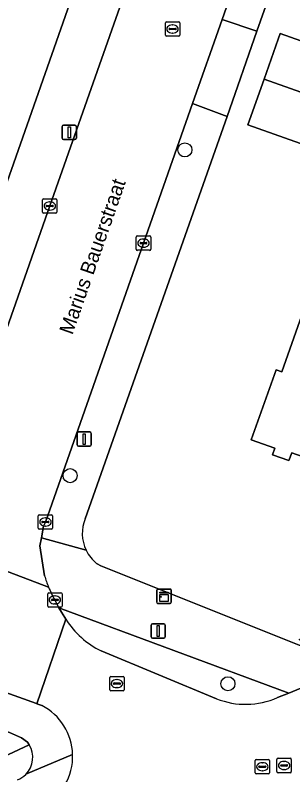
# Model space of a CAD drawing. Extents: x 163266 to 164362, y 381528 to 382286.
# Drawn here: x 163785.5 to 163804.8, y 381685.3 to 381738.1 of the extents above; entities that cross this region are included whole.
import ezdxf

# ---------------------------------------------------------------- set-up
doc = ezdxf.new("R2010")
doc.units = 0
for name, color, linetype in [('IMGEO_Boom', 7, 'Continuous'), ('IMGEO_Erf', 7, 'Continuous'), ('IMGEO_Groenvoorziening', 7, 'Continuous'), ('IMGEO_Kast', 7, 'Continuous'), ('IMGEO_Kolk', 7, 'Continuous'), ('IMGEO_Lichtmast', 7, 'Continuous'), ('IMGEO_Openbare_ruimte_label', 7, 'Continuous'), ('IMGEO_Pand', 7, 'Continuous'), ('IMGEO_Rijbaan_lokaal_open', 7, 'Continuous'), ('IMGEO_Rioolput', 7, 'Continuous'), ('IMGEO_Voetpad_open', 7, 'Continuous')]:
    doc.layers.add(name, color=color, linetype=linetype)

msp = doc.modelspace()

# ---------------------------------------------------------------- linework, layer by layer
at = {"layer": 'IMGEO_Boom'}
for centre in [(163797.269, 381728.696), (163789.28, 381706.058), (163800.268, 381691.599)]:
    msp.add_circle(centre, 0.489, dxfattribs=at)
at = {"layer": 'IMGEO_Erf'}
for points in [[(163812.165, 381764.712), (163806.923, 381750), (163802.269, 381736.937), (163800.206, 381731.005), (163790.326, 381703.056)], [(163777.847, 381706.456), (163793.157, 381750)], [(163791.151, 381699.94), (163791.408, 381699.801), (163806.152, 381693.919), (163806.177, 381693.979), (163805.225, 381694.676), (163831.794, 381705.491), (163841.15, 381710.28)]]:
    msp.add_lwpolyline(points, dxfattribs=at)
for points in [[(163812.472, 381727.394), (163810.675, 381728.03), (163810.431, 381727.341), (163801.659, 381730.443), (163802.779, 381733.609), (163803.764, 381736.396), (163803.897, 381736.771), (163812.668, 381733.669), (163811.55, 381730.506), (163813.348, 381729.87)], [(163815.301, 381718.07), (163813.331, 381712.499), (163812.084, 381712.94), (163809.721, 381706.258), (163811.07, 381705.781), (163810.948, 381705.435), (163804.707, 381707.643), (163804.516, 381707.104), (163803.376, 381707.507), (163803.537, 381707.961), (163801.891, 381708.542), (163803.614, 381713.412), (163804.015, 381713.27), (163806.641, 381720.695), (163806.167, 381720.862), (163806.29, 381721.211), (163808.642, 381720.379), (163808.82, 381720.884), (163809.958, 381720.482), (163809.794, 381720.018)]]:
    msp.add_lwpolyline(points, close=True, dxfattribs=at)
for centre, radius, start, end in [((163792.797, 381702.044), 2.67, 157.7302, 205.8989), ((163792.792, 381702.037), 2.663, 205.7933, 231.9423)]:
    msp.add_arc(centre, radius, start, end, dxfattribs=at)
at = {"layer": 'IMGEO_Groenvoorziening'}
for points in [[(163788.503, 381696.878), (163788.683, 381696.565), (163788.902, 381696.202), (163788.981, 381696.076)], [(163803.705, 381690.635), (163804.494, 381690.943), (163788.503, 381696.878)], [(163791.444, 381693.885), (163799.475, 381690.558)], [(163786.431, 381687.36), (163746.827, 381668.861), (163743.582, 381666.907), (163741.092, 381665.064), (163738.545, 381663.071), (163732.674, 381659.172), (163735.245, 381658.18)]]:
    msp.add_lwpolyline(points, dxfattribs=at)
msp.add_lwpolyline([(163786.431, 381687.36), (163786.311, 381687.532), (163785.889, 381687.845), (163785.054, 381688.219), (163774.893, 381691.766), (163774.456, 381690.384), (163772.402, 381684.557), (163769.505, 381685.578), (163766.609, 381686.599), (163763.712, 381687.62), (163760.816, 381688.64), (163757.919, 381689.661), (163755.022, 381690.682), (163752.126, 381691.703), (163749.229, 381692.724), (163745.303, 381694.051), (163732.674, 381659.172), (163738.545, 381663.071), (163741.092, 381665.064), (163743.582, 381666.907), (163746.827, 381668.861)], close=True, dxfattribs=at)
for centre, radius, start, end in [((163794.096, 381699.346), 6.071, 212.5919, 244.0977), ((163801.499, 381695.612), 5.445, 248.1798, 293.9059), ((163784.99, 381686.482), 1.687, 315.6611, 31.359), ((163784.982, 381686.499), 1.705, 291.6153, 315.4489)]:
    msp.add_arc(centre, radius, start, end, dxfattribs=at)
at = {"layer": 'IMGEO_Kast'}
for p, q in [((163795.32, 381697.255), (163795.32, 381698.096)), ((163795.32, 381698.096), (163795.32, 381697.255)), ((163795.395, 381698.18), (163796.236, 381698.18)), ((163796.236, 381698.18), (163795.395, 381698.18)), ((163796.32, 381698.105), (163796.32, 381697.264)), ((163796.32, 381697.264), (163796.32, 381698.105)), ((163796.245, 381697.18), (163795.404, 381697.18)), ((163795.404, 381697.18), (163796.245, 381697.18))]:
    msp.add_line(p, q, dxfattribs=at)
for points in [[(163795.515, 381697.97), (163796.115, 381697.97), (163796.115, 381697.885), (163795.515, 381697.885), (163795.515, 381697.97)], [(163795.515, 381697.795), (163796.115, 381697.795), (163796.115, 381697.306), (163795.515, 381697.306), (163795.515, 381697.795)]]:
    msp.add_lwpolyline(points, dxfattribs=at)
msp.add_circle((163795.599, 381697.644), 0.0377, dxfattribs=at)
for centre, start, end in [((163795.398, 381698.102), 92.4484, 184.2845), ((163795.398, 381698.102), 92.4484, 184.2845), ((163796.242, 381698.102), 2.4484, 94.2845), ((163796.242, 381698.102), 2.4484, 94.2845), ((163795.398, 381697.258), 182.4484, 274.2845), ((163795.398, 381697.258), 182.4484, 274.2845), ((163796.242, 381697.258), 272.4484, 4.2845), ((163796.242, 381697.258), 272.4484, 4.2845)]:
    msp.add_arc(centre, 0.0779, start, end, dxfattribs=at)
at = {"layer": 'IMGEO_Kolk'}
for p, q in [((163787.362, 381724.37), (163787.362, 381725.222)), ((163787.437, 381725.296), (163788.289, 381725.296)), ((163787.664, 381724.839), (163788.062, 381724.839)), ((163787.85, 381725.076), (163787.875, 381725.076)), ((163788.363, 381725.222), (163788.363, 381724.37)), ((163787.621, 381724.79), (163787.621, 381724.802)), ((163788.059, 381724.753), (163787.661, 381724.753)), ((163787.873, 381724.516), (163787.848, 381724.516)), ((163788.105, 381724.802), (163788.105, 381724.79)), ((163788.289, 381724.296), (163787.437, 381724.296)), ((163793.886, 381721.789), (163793.886, 381722.641)), ((163793.961, 381722.715), (163794.813, 381722.715)), ((163794.145, 381722.209), (163794.145, 381722.221)), ((163794.188, 381722.258), (163794.586, 381722.258)), ((163794.374, 381722.495), (163794.399, 381722.495)), ((163794.629, 381722.221), (163794.629, 381722.209)), ((163794.887, 381722.641), (163794.887, 381721.789)), ((163794.813, 381721.715), (163793.961, 381721.715)), ((163794.583, 381722.172), (163794.185, 381722.172)), ((163794.397, 381721.935), (163794.372, 381721.935)), ((163787.061, 381702.411), (163787.061, 381703.263)), ((163787.136, 381703.337), (163787.988, 381703.337)), ((163788.062, 381703.263), (163788.062, 381702.411)), ((163787.32, 381702.831), (163787.32, 381702.843)), ((163787.758, 381702.794), (163787.36, 381702.794)), ((163787.363, 381702.88), (163787.761, 381702.88)), ((163787.549, 381703.117), (163787.574, 381703.117)), ((163787.804, 381702.843), (163787.804, 381702.831)), ((163787.988, 381702.337), (163787.136, 381702.337)), ((163787.572, 381702.557), (163787.547, 381702.557)), ((163787.792, 381697.923), (163788.644, 381697.923)), ((163787.717, 381696.997), (163787.717, 381697.849)), ((163787.976, 381697.417), (163787.976, 381697.429)), ((163788.019, 381697.466), (163788.417, 381697.466)), ((163788.205, 381697.703), (163788.23, 381697.703)), ((163788.46, 381697.429), (163788.46, 381697.417)), ((163788.718, 381697.849), (163788.718, 381696.997)), ((163788.644, 381696.923), (163787.792, 381696.923)), ((163788.414, 381697.38), (163788.016, 381697.38)), ((163788.228, 381697.143), (163788.203, 381697.143))]:
    msp.add_line(p, q, dxfattribs=at)
for points in [[(163787.362, 381724.37), (163787.362, 381725.222)], [(163787.437, 381725.296), (163788.289, 381725.296)], [(163788.363, 381725.222), (163788.363, 381724.37)], [(163788.289, 381724.296), (163787.437, 381724.296)], [(163793.886, 381721.789), (163793.886, 381722.641)], [(163793.961, 381722.715), (163794.813, 381722.715)], [(163794.887, 381722.641), (163794.887, 381721.789)], [(163794.813, 381721.715), (163793.961, 381721.715)], [(163787.061, 381702.411), (163787.061, 381703.263)], [(163787.136, 381703.337), (163787.988, 381703.337)], [(163788.062, 381703.263), (163788.062, 381702.411)], [(163787.988, 381702.337), (163787.136, 381702.337)], [(163787.792, 381697.923), (163788.644, 381697.923)], [(163787.717, 381696.997), (163787.717, 381697.849)], [(163788.718, 381697.849), (163788.718, 381696.997)], [(163788.644, 381696.923), (163787.792, 381696.923)]]:
    msp.add_lwpolyline(points, dxfattribs=at)
for centre, radius, start, end in [((163787.439, 381725.22), 0.0765, 91.552, 178.448), ((163787.439, 381725.22), 0.0765, 91.552, 178.448), ((163787.661, 381724.799), 0.0403, 85.8775, 175.7526), ((163788.066, 381724.801), 0.0386, 1.7309, 96.639), ((163788.287, 381725.22), 0.0765, 1.552, 88.448), ((163788.287, 381725.22), 0.0765, 1.552, 88.448), ((163787.439, 381724.372), 0.0765, 181.552, 268.448), ((163787.439, 381724.372), 0.0765, 181.552, 268.448), ((163787.658, 381724.789), 0.0366, 178.938, 274.7102), ((163788.062, 381724.796), 0.043, 264.8664, 352.4533), ((163788.287, 381724.372), 0.0765, 271.552, 358.448), ((163788.287, 381724.372), 0.0765, 271.552, 358.448), ((163793.963, 381722.639), 0.0765, 91.552, 178.448), ((163793.963, 381722.639), 0.0765, 91.552, 178.448), ((163794.185, 381722.218), 0.0403, 85.8775, 175.7526), ((163794.182, 381722.208), 0.0366, 178.938, 274.7102), ((163794.586, 381722.215), 0.043, 264.8664, 352.4533), ((163794.59, 381722.22), 0.0386, 1.7309, 96.639), ((163794.811, 381722.639), 0.0765, 1.552, 88.448), ((163794.811, 381722.639), 0.0765, 1.552, 88.448), ((163793.963, 381721.791), 0.0765, 181.552, 268.448), ((163793.963, 381721.791), 0.0765, 181.552, 268.448), ((163794.811, 381721.791), 0.0765, 271.552, 358.448), ((163794.811, 381721.791), 0.0765, 271.552, 358.448), ((163787.138, 381703.261), 0.0765, 91.552, 178.448), ((163787.138, 381703.261), 0.0765, 91.552, 178.448), ((163787.986, 381703.261), 0.0765, 1.552, 88.448), ((163787.986, 381703.261), 0.0765, 1.552, 88.448), ((163787.36, 381702.84), 0.0403, 85.8775, 175.7526), ((163787.357, 381702.83), 0.0366, 178.938, 274.7102), ((163787.761, 381702.837), 0.043, 264.8664, 352.4533), ((163787.765, 381702.842), 0.0386, 1.7309, 96.639), ((163787.138, 381702.413), 0.0765, 181.552, 268.448), ((163787.138, 381702.413), 0.0765, 181.552, 268.448), ((163787.986, 381702.413), 0.0765, 271.552, 358.448), ((163787.986, 381702.413), 0.0765, 271.552, 358.448), ((163787.794, 381697.847), 0.0765, 91.552, 178.448), ((163787.794, 381697.847), 0.0765, 91.552, 178.448), ((163788.642, 381697.847), 0.0765, 1.552, 88.448), ((163788.642, 381697.847), 0.0765, 1.552, 88.448), ((163788.016, 381697.426), 0.0403, 85.8775, 175.7526), ((163788.013, 381697.416), 0.0366, 178.938, 274.7102), ((163788.417, 381697.423), 0.043, 264.8664, 352.4533), ((163788.421, 381697.428), 0.0386, 1.7309, 96.639), ((163787.794, 381696.999), 0.0765, 181.552, 268.448), ((163787.794, 381696.999), 0.0765, 181.552, 268.448), ((163788.642, 381696.999), 0.0765, 271.552, 358.448), ((163788.642, 381696.999), 0.0765, 271.552, 358.448)]:
    msp.add_arc(centre, radius, start, end, dxfattribs=at)
for centre, major_axis, ratio, start_param, end_param in [((163787.849, 381724.796), (-0.387, 0.002), 0.722429, 4.712389, 7.853982), ((163787.874, 381724.796), (-0.39, 0.002), 0.717154, 1.570796, 4.712389), ((163794.373, 381722.215), (-0.387, 0.002), 0.722429, 4.712389, 7.853982), ((163794.398, 381722.215), (-0.39, 0.002), 0.717154, 1.570796, 4.712389), ((163787.548, 381702.837), (-0.387, 0.002), 0.722429, 4.712389, 7.853982), ((163787.573, 381702.837), (-0.39, 0.002), 0.717154, 1.570796, 4.712389), ((163788.204, 381697.423), (-0.387, 0.002), 0.722429, 4.712389, 7.853982), ((163788.229, 381697.423), (-0.39, 0.002), 0.717154, 1.570796, 4.712389)]:
    msp.add_ellipse(centre, major_axis=major_axis, ratio=ratio, start_param=start_param, end_param=end_param, dxfattribs=at)
at = {"layer": 'IMGEO_Lichtmast'}
for p, q in [((163788.725, 381729.513), (163788.725, 381730.313)), ((163788.725, 381730.313), (163788.725, 381729.513)), ((163788.825, 381730.413), (163789.615, 381730.413)), ((163789.615, 381730.413), (163788.825, 381730.413)), ((163789.715, 381730.313), (163789.715, 381729.513)), ((163789.715, 381729.513), (163789.715, 381730.313)), ((163789.615, 381729.413), (163788.825, 381729.413)), ((163788.825, 381729.413), (163789.615, 381729.413)), ((163789.864, 381709.097), (163790.654, 381709.097)), ((163790.654, 381709.097), (163789.864, 381709.097)), ((163789.764, 381708.197), (163789.764, 381708.997)), ((163789.764, 381708.997), (163789.764, 381708.197)), ((163790.754, 381708.997), (163790.754, 381708.197)), ((163790.754, 381708.197), (163790.754, 381708.997)), ((163790.654, 381708.097), (163789.864, 381708.097)), ((163789.864, 381708.097), (163790.654, 381708.097)), ((163794.915, 381694.86), (163794.915, 381695.66)), ((163794.915, 381695.66), (163794.915, 381694.86)), ((163795.015, 381695.76), (163795.805, 381695.76)), ((163795.805, 381695.76), (163795.015, 381695.76)), ((163795.905, 381695.66), (163795.905, 381694.86)), ((163795.905, 381694.86), (163795.905, 381695.66)), ((163795.805, 381694.76), (163795.015, 381694.76)), ((163795.015, 381694.76), (163795.805, 381694.76))]:
    msp.add_line(p, q, dxfattribs=at)
for points in [[(163789.145, 381730.288), (163789.295, 381730.288), (163789.295, 381729.538), (163789.145, 381729.538), (163789.145, 381730.288)], [(163790.184, 381708.972), (163790.334, 381708.972), (163790.334, 381708.222), (163790.184, 381708.222), (163790.184, 381708.972)], [(163795.335, 381695.635), (163795.485, 381695.635), (163795.485, 381694.885), (163795.335, 381694.885), (163795.335, 381695.635)]]:
    msp.add_lwpolyline(points, dxfattribs=at)
for centre, start, end in [((163788.825, 381730.313), 90, 180), ((163788.825, 381730.313), 90, 180), ((163789.615, 381730.313), 0, 90), ((163789.615, 381730.313), 360, 90), ((163788.825, 381729.513), 180, 270), ((163788.825, 381729.513), 180, 270), ((163789.615, 381729.513), 270, 0), ((163789.615, 381729.513), 270, 0), ((163789.864, 381708.997), 90, 180), ((163789.864, 381708.997), 90, 180), ((163790.654, 381708.997), 0, 90), ((163790.654, 381708.997), 360, 90), ((163789.864, 381708.197), 180, 270), ((163789.864, 381708.197), 180, 270), ((163790.654, 381708.197), 270, 0), ((163790.654, 381708.197), 270, 0), ((163795.015, 381695.66), 90, 180), ((163795.015, 381695.66), 90, 180), ((163795.805, 381695.66), 0, 90), ((163795.805, 381695.66), 360, 90), ((163795.015, 381694.86), 180, 270), ((163795.015, 381694.86), 180, 270), ((163795.805, 381694.86), 270, 0), ((163795.805, 381694.86), 270, 0)]:
    msp.add_arc(centre, 0.1, start, end, dxfattribs=at)
at = {"layer": 'IMGEO_Pand'}
for points in [[(163811.55, 381730.506), (163812.668, 381733.669), (163803.897, 381736.771), (163803.764, 381736.396), (163802.779, 381733.609)], [(163802.779, 381733.609), (163801.659, 381730.443), (163810.431, 381727.341), (163810.675, 381728.03), (163811.55, 381730.506)], [(163810.948, 381705.435), (163811.07, 381705.781), (163809.721, 381706.258), (163812.084, 381712.94), (163813.331, 381712.499), (163815.301, 381718.07), (163809.794, 381720.018), (163809.958, 381720.482), (163808.82, 381720.884), (163808.642, 381720.379), (163806.29, 381721.211), (163806.167, 381720.862), (163806.641, 381720.695), (163804.015, 381713.27), (163803.614, 381713.412), (163801.891, 381708.542), (163803.537, 381707.961), (163803.376, 381707.507), (163804.516, 381707.104), (163804.707, 381707.643)]]:
    msp.add_lwpolyline(points, close=True, dxfattribs=at)
at = {"layer": 'IMGEO_Rijbaan_lokaal_open'}
for points in [[(163802.834, 381767.295), (163802.49, 381766.272), (163795.328, 381745.996), (163787.863, 381724.796), (163781.038, 381705.454), (163780.903, 381705.075)], [(163787.506, 381699.094), (163787.177, 381701.17), (163787.28, 381701.743), (163787.425, 381702.556), (163787.562, 381702.837), (163794.387, 381722.215), (163797.797, 381731.907), (163799.856, 381737.758), (163809.414, 381764.894)], [(163772.976, 381702.56), (163770.962, 381703.367), (163761.526, 381706.688), (163736.775, 381715.394), (163730.618, 381717.411), (163729.531, 381717.818), (163727.274, 381711.194), (163728.377, 381710.805), (163738.302, 381707.424), (163744.653, 381705.184), (163752.662, 381702.365), (163775.707, 381694.245), (163775.935, 381694.11), (163781.991, 381691.984), (163786.943, 381690.215), (163786.955, 381690.211), (163788.981, 381696.076), (163788.902, 381696.202), (163788.683, 381696.565), (163788.503, 381696.878), (163788.218, 381697.423)], [(163787.782, 381698.313), (163777.894, 381702.062)], [(163777.894, 381702.062), (163787.782, 381698.313)], [(163788.981, 381696.076), (163786.955, 381690.211), (163787.32, 381690.079)], [(163813.682, 381689.801), (163815.256, 381690.453), (163813.448, 381694.664), (163808.955, 381692.801), (163804.494, 381690.943), (163803.705, 381690.635)], [(163799.475, 381690.558), (163791.444, 381693.885)]]:
    msp.add_lwpolyline(points, dxfattribs=at)
for centre, radius, start, end in [((163794.165, 381701.008), 6.929, 196.0361, 202.89), ((163795.037, 381701.315), 7.852, 202.4813, 209.718), ((163794.096, 381699.346), 6.071, 212.5919, 244.0977), ((163801.499, 381695.612), 5.445, 248.1798, 293.9059), ((163785.498, 381686.563), 3.96, 1.7948, 62.6038), ((163785.498, 381686.561), 3.96, 297.5918, 1.8248)]:
    msp.add_arc(centre, radius, start, end, dxfattribs=at)
at = {"layer": 'IMGEO_Rioolput'}
for p, q in [((163795.91, 381736.668), (163795.91, 381737.52)), ((163795.985, 381737.594), (163796.837, 381737.594)), ((163796.911, 381737.52), (163796.911, 381736.668)), ((163796.169, 381737.088), (163796.169, 381737.1)), ((163796.607, 381737.051), (163796.209, 381737.051)), ((163796.212, 381737.137), (163796.61, 381737.137)), ((163796.398, 381737.374), (163796.423, 381737.374)), ((163796.653, 381737.1), (163796.653, 381737.088)), ((163796.837, 381736.594), (163795.985, 381736.594)), ((163796.421, 381736.814), (163796.396, 381736.814)), ((163792.036, 381691.181), (163792.036, 381692.033)), ((163792.111, 381692.107), (163792.963, 381692.107)), ((163792.295, 381691.601), (163792.295, 381691.613)), ((163792.338, 381691.65), (163792.736, 381691.65)), ((163792.524, 381691.887), (163792.549, 381691.887)), ((163792.779, 381691.613), (163792.779, 381691.601)), ((163793.037, 381692.033), (163793.037, 381691.181)), ((163792.963, 381691.107), (163792.111, 381691.107)), ((163792.733, 381691.564), (163792.335, 381691.564)), ((163792.547, 381691.327), (163792.522, 381691.327)), ((163802.238, 381686.332), (163803.09, 381686.332)), ((163803.677, 381685.492), (163803.677, 381686.344)), ((163803.752, 381686.418), (163804.604, 381686.418)), ((163804.678, 381686.344), (163804.678, 381685.492)), ((163802.163, 381685.406), (163802.163, 381686.258)), ((163802.422, 381685.826), (163802.422, 381685.838)), ((163802.86, 381685.789), (163802.462, 381685.789)), ((163802.465, 381685.875), (163802.863, 381685.875)), ((163802.651, 381686.112), (163802.676, 381686.112)), ((163802.906, 381685.838), (163802.906, 381685.826)), ((163803.164, 381686.258), (163803.164, 381685.406)), ((163803.936, 381685.912), (163803.936, 381685.924)), ((163804.374, 381685.875), (163803.976, 381685.875)), ((163803.979, 381685.961), (163804.377, 381685.961)), ((163804.165, 381686.198), (163804.19, 381686.198)), ((163804.42, 381685.924), (163804.42, 381685.912)), ((163803.09, 381685.332), (163802.238, 381685.332)), ((163802.674, 381685.552), (163802.649, 381685.552)), ((163804.604, 381685.418), (163803.752, 381685.418)), ((163804.188, 381685.638), (163804.163, 381685.638))]:
    msp.add_line(p, q, dxfattribs=at)
for points in [[(163795.91, 381736.668), (163795.91, 381737.52)], [(163795.985, 381737.594), (163796.837, 381737.594)], [(163796.911, 381737.52), (163796.911, 381736.668)], [(163796.837, 381736.594), (163795.985, 381736.594)], [(163792.036, 381691.181), (163792.036, 381692.033)], [(163792.111, 381692.107), (163792.963, 381692.107)], [(163793.037, 381692.033), (163793.037, 381691.181)], [(163792.963, 381691.107), (163792.111, 381691.107)], [(163802.238, 381686.332), (163803.09, 381686.332)], [(163803.677, 381685.492), (163803.677, 381686.344)], [(163803.752, 381686.418), (163804.604, 381686.418)], [(163804.678, 381686.344), (163804.678, 381685.492)], [(163802.163, 381685.406), (163802.163, 381686.258)], [(163803.164, 381686.258), (163803.164, 381685.406)], [(163803.09, 381685.332), (163802.238, 381685.332)], [(163804.604, 381685.418), (163803.752, 381685.418)]]:
    msp.add_lwpolyline(points, dxfattribs=at)
for centre, radius, start, end in [((163795.987, 381737.518), 0.0765, 91.552, 178.448), ((163795.987, 381737.518), 0.0765, 91.552, 178.448), ((163796.835, 381737.518), 0.0765, 1.552, 88.448), ((163796.835, 381737.518), 0.0765, 1.552, 88.448), ((163796.209, 381737.097), 0.0403, 85.8775, 175.7526), ((163796.206, 381737.087), 0.0366, 178.938, 274.7102), ((163796.61, 381737.094), 0.043, 264.8664, 352.4533), ((163796.614, 381737.099), 0.0386, 1.7309, 96.639), ((163795.987, 381736.67), 0.0765, 181.552, 268.448), ((163795.987, 381736.67), 0.0765, 181.552, 268.448), ((163796.835, 381736.67), 0.0765, 271.552, 358.448), ((163796.835, 381736.67), 0.0765, 271.552, 358.448), ((163792.113, 381692.031), 0.0765, 91.552, 178.448), ((163792.113, 381692.031), 0.0765, 91.552, 178.448), ((163792.335, 381691.61), 0.0403, 85.8775, 175.7526), ((163792.332, 381691.6), 0.0366, 178.938, 274.7102), ((163792.736, 381691.607), 0.043, 264.8664, 352.4533), ((163792.74, 381691.612), 0.0386, 1.7309, 96.639), ((163792.961, 381692.031), 0.0765, 1.552, 88.448), ((163792.961, 381692.031), 0.0765, 1.552, 88.448), ((163792.113, 381691.183), 0.0765, 181.552, 268.448), ((163792.113, 381691.183), 0.0765, 181.552, 268.448), ((163792.961, 381691.183), 0.0765, 271.552, 358.448), ((163792.961, 381691.183), 0.0765, 271.552, 358.448), ((163802.24, 381686.256), 0.0765, 91.552, 178.448), ((163802.24, 381686.256), 0.0765, 91.552, 178.448), ((163803.088, 381686.256), 0.0765, 1.552, 88.448), ((163803.088, 381686.256), 0.0765, 1.552, 88.448), ((163803.754, 381686.342), 0.0765, 91.552, 178.448), ((163803.754, 381686.342), 0.0765, 91.552, 178.448), ((163804.602, 381686.342), 0.0765, 1.552, 88.448), ((163804.602, 381686.342), 0.0765, 1.552, 88.448), ((163802.462, 381685.835), 0.0403, 85.8775, 175.7526), ((163802.459, 381685.825), 0.0366, 178.938, 274.7102), ((163802.863, 381685.832), 0.043, 264.8664, 352.4533), ((163802.867, 381685.837), 0.0386, 1.7309, 96.639), ((163803.976, 381685.921), 0.0403, 85.8775, 175.7526), ((163803.973, 381685.911), 0.0366, 178.938, 274.7102), ((163804.377, 381685.918), 0.043, 264.8664, 352.4533), ((163804.381, 381685.923), 0.0386, 1.7309, 96.639), ((163802.24, 381685.408), 0.0765, 181.552, 268.448), ((163802.24, 381685.408), 0.0765, 181.552, 268.448), ((163803.088, 381685.408), 0.0765, 271.552, 358.448), ((163803.088, 381685.408), 0.0765, 271.552, 358.448), ((163803.754, 381685.494), 0.0765, 181.552, 268.448), ((163803.754, 381685.494), 0.0765, 181.552, 268.448), ((163804.602, 381685.494), 0.0765, 271.552, 358.448), ((163804.602, 381685.494), 0.0765, 271.552, 358.448)]:
    msp.add_arc(centre, radius, start, end, dxfattribs=at)
for centre, major_axis, ratio, start_param, end_param in [((163796.397, 381737.094), (-0.387, 0.002), 0.722429, 4.712389, 7.853982), ((163796.422, 381737.094), (-0.39, 0.002), 0.717154, 1.570796, 4.712389), ((163792.523, 381691.607), (-0.387, 0.002), 0.722429, 4.712389, 7.853982), ((163792.548, 381691.607), (-0.39, 0.002), 0.717154, 1.570796, 4.712389), ((163802.65, 381685.832), (-0.387, 0.002), 0.722429, 4.712389, 7.853982), ((163802.675, 381685.832), (-0.39, 0.002), 0.717154, 1.570796, 4.712389), ((163804.164, 381685.918), (-0.387, 0.002), 0.722429, 4.712389, 7.853982), ((163804.189, 381685.918), (-0.39, 0.002), 0.717154, 1.570796, 4.712389)]:
    msp.add_ellipse(centre, major_axis=major_axis, ratio=ratio, start_param=start_param, end_param=end_param, dxfattribs=at)
at = {"layer": 'IMGEO_Voetpad_open'}
for points in [[(163799.834, 381768.991), (163793.157, 381750), (163777.847, 381706.456)], [(163780.903, 381705.075), (163781.038, 381705.454), (163787.863, 381724.796), (163795.328, 381745.996), (163802.49, 381766.272)], [(163809.414, 381764.894), (163799.856, 381737.758), (163802.269, 381736.937), (163806.923, 381750), (163812.165, 381764.712)], [(163800.206, 381731.005), (163797.797, 381731.907), (163794.387, 381722.215), (163787.562, 381702.837), (163787.425, 381702.556), (163787.28, 381701.743), (163790.395, 381700.878)], [(163790.326, 381703.056), (163800.206, 381731.005)], [(163790.395, 381700.878), (163787.28, 381701.743), (163787.177, 381701.17), (163787.506, 381699.094)], [(163788.218, 381697.423), (163788.503, 381696.878), (163804.494, 381690.943), (163808.955, 381692.801), (163806.152, 381693.919), (163791.408, 381699.801)], [(163791.408, 381699.801), (163791.151, 381699.94)], [(163787.32, 381690.079), (163786.955, 381690.211), (163786.943, 381690.215), (163781.991, 381691.984), (163775.935, 381694.11), (163775.707, 381694.245), (163774.893, 381691.766), (163785.054, 381688.219), (163785.889, 381687.845), (163786.311, 381687.532), (163786.431, 381687.36)], [(163789.456, 381686.687), (163786.197, 381685.303)], [(163786.197, 381685.303), (163789.456, 381686.687)]]:
    msp.add_lwpolyline(points, dxfattribs=at)
msp.add_lwpolyline([(163802.269, 381736.937), (163799.856, 381737.758), (163797.797, 381731.907), (163800.206, 381731.005)], close=True, dxfattribs=at)
for centre, radius, start, end in [((163792.797, 381702.044), 2.67, 157.7302, 205.8989), ((163792.792, 381702.037), 2.663, 205.7933, 231.9423), ((163794.165, 381701.008), 6.929, 196.0361, 202.89), ((163795.037, 381701.315), 7.852, 202.4813, 209.718), ((163785.498, 381686.563), 3.96, 1.7948, 62.6038), ((163784.99, 381686.482), 1.687, 315.6611, 31.359), ((163785.498, 381686.561), 3.96, 297.5918, 1.8248), ((163784.982, 381686.499), 1.705, 291.6153, 315.4489)]:
    msp.add_arc(centre, radius, start, end, dxfattribs=at)

# ---------------------------------------------------------------- texts
at = {"layer": 'IMGEO_Openbare_ruimte_label'}
msp.add_text('Marius Bauerstraat', height=1, rotation=70.7316, dxfattribs=at).set_placement((163789.437, 381715.797))

doc.saveas('drawing.dxf')
